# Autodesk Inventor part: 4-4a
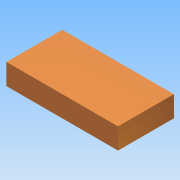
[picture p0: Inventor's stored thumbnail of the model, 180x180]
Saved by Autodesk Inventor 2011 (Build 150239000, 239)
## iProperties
Created: 2014-03
Part Number: 4-4a
Document SubType Name: Modeling
Designer: Administrator
Density: 1 g/cm^3
Author: Administrator
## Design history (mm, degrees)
sketch "草图1"
  geometry: L1 (-40, 20)-(40, 20); L2 (40, 20)-(40, -20); L3 (40, -20)-(-40, -20); L4 (-40, -20)-(-40, 20); 3 further points
  constraints: 8 end point, 2 midpoint, 2 parallel, 1 horizontal, 1 horizontal alignment, 1 perpendicular, 1 vertical alignment
  dimensions: "d0" = 80 distance of L1.start L1.end; "d1" = 40 distance of L3.end L1.start
extrude "拉伸1" new body sketch "草图1" distance "d2" = 15; taper "d3" = 0 deg
node "实体1"
